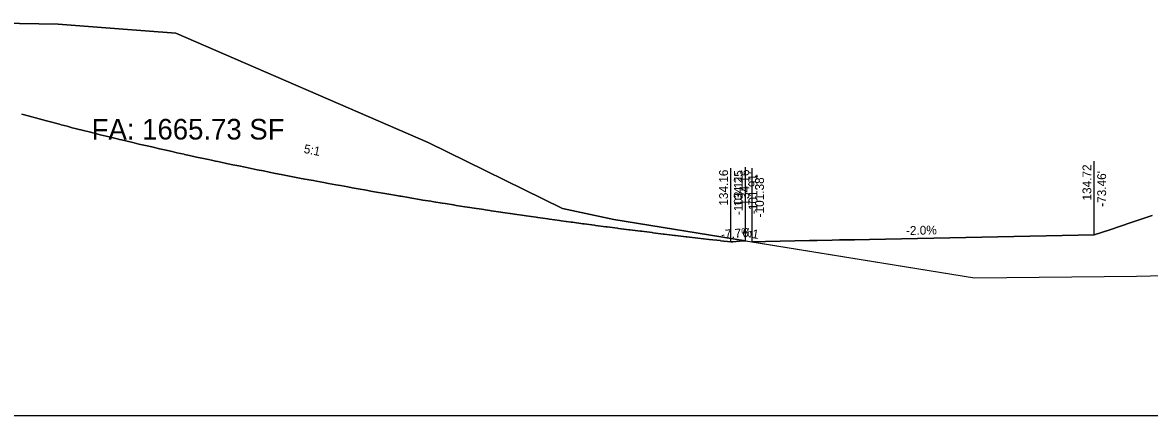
# Model space of a CAD drawing. Extents: x -26 to 4403, y -13 to 9578.
# Drawn here: x 2089.1 to 2181, y 0 to 32 of the extents above; entities that cross this region are included whole.
import ezdxf

# ---------------------------------------------------------------- set-up
doc = ezdxf.new("R2010")
doc.units = 0
for name, color, linetype in [('CONST_DCH', 7, 'Continuous'), ('DRAINAGE_SPUR_DIKES', 7, 'Continuous'), ('DTM_CORRIDOR', 7, 'Continuous'), ('DTM_X_GROUND', 7, 'Continuous'), ('XS_CELL', 7, 'Continuous'), ('XS_M_SHAPES_EARTHWORK', 7, 'Continuous'), ('XS_P_GROUND', 7, 'Continuous'), ('XS_P_TX_CLEARZONE', 7, 'Continuous'), ('XS_P_TX_FS_BS', 7, 'Continuous'), ('XS_SHEET_EW_TX_AREA', 7, 'Continuous')]:
    doc.layers.add(name, color=color, linetype=linetype)

msp = doc.modelspace()

# ---------------------------------------------------------------- linework, layer by layer
at = {"layer": 'DTM_X_GROUND'}
msp.add_lwpolyline([(2000, 18.081), (2016.738, 18.017), (2021.336, 18.271), (2026.377, 18.668), (2031.376, 19.287), (2044.087, 25.683), (2054.877, 30.415), (2060.086, 31.086), (2066.447, 31.939), (2073.829, 32.038), (2079.891, 32.016), (2085.664, 32.011), (2091.991, 31.895), (2096.952, 31.53), (2101.603, 31.182), (2122.191, 22.251), (2133.153, 16.884), (2137.339, 15.992), (2166.759, 11.226), (2179.976, 11.364), (2202.58, 11.905)], dxfattribs=at)
at = {"layer": 'XS_CELL'}
msp.add_line((2000, 0), (2250, 0), dxfattribs=at)
at = {"layer": 'XS_M_SHAPES_EARTHWORK'}
for points in [[(2085.664, 32.011), (2091.991, 31.895), (2096.952, 31.53), (2101.603, 31.182), (2122.191, 22.251), (2133.153, 16.884), (2137.339, 15.992), (2148.092, 14.25), (2147.869, 14.233), (2147.052, 14.17), (2146.955, 14.163), (2146.891, 14.158), (2146.04, 14.252), (2146.033, 14.253), (2145.123, 14.355), (2145.108, 14.357), (2144.204, 14.46), (2144.181, 14.463), (2143.284, 14.567), (2143.252, 14.571), (2142.361, 14.676), (2142.321, 14.681), (2141.437, 14.787), (2141.388, 14.793), (2140.511, 14.9), (2140.454, 14.908), (2139.584, 15.015), (2139.517, 15.024), (2138.654, 15.132), (2138.578, 15.142), (2137.723, 15.252), (2137.637, 15.263), (2136.789, 15.373), (2136.694, 15.385), (2135.854, 15.496), (2135.749, 15.51), (2134.916, 15.621), (2134.802, 15.636), (2133.977, 15.748), (2133.852, 15.765), (2133.035, 15.877), (2132.901, 15.896), (2132.091, 16.009), (2131.946, 16.029), (2131.145, 16.142), (2130.99, 16.164), (2130.197, 16.277), (2130.031, 16.302), (2129.247, 16.415), (2129.07, 16.441), (2128.294, 16.555), (2128.106, 16.583), (2127.339, 16.697), (2127.234, 16.712), (2126.833, 16.773), (2126.736, 16.787), (2126.345, 16.846), (2126.134, 16.878), (2125.412, 16.987), (2125.189, 17.022), (2124.487, 17.13), (2124.252, 17.167), (2123.57, 17.274), (2123.323, 17.314), (2122.66, 17.42), (2122.401, 17.462), (2121.757, 17.568), (2121.485, 17.613), (2120.859, 17.717), (2120.575, 17.766), (2119.966, 17.869), (2119.94, 17.874), (2119.887, 17.883), (2119.616, 17.93), (2118.973, 18.041), (2118.662, 18.096), (2117.977, 18.215), (2117.651, 18.273), (2116.987, 18.39), (2116.647, 18.451), (2116.003, 18.565), (2115.649, 18.629), (2115.025, 18.742), (2114.656, 18.809), (2114.051, 18.92), (2113.667, 18.991), (2113.082, 19.099), (2112.824, 19.148), (2112.454, 19.217), (2112.312, 19.244), (2112.12, 19.28), (2111.705, 19.36), (2111.161, 19.463), (2110.73, 19.547), (2110.196, 19.651), (2109.748, 19.739), (2109.223, 19.843), (2108.759, 19.936), (2108.244, 20.039), (2107.762, 20.137), (2107.257, 20.239), (2106.757, 20.342), (2106.263, 20.444), (2105.745, 20.552), (2105.262, 20.653), (2105.032, 20.702), (2104.827, 20.745), (2104.52, 20.81), (2104.276, 20.862), (2103.72, 20.982), (2103.296, 21.073), (2102.721, 21.199), (2102.304, 21.291), (2102.285, 21.295), (2102.272, 21.298), (2101.695, 21.427), (2101.3, 21.514), (2100.683, 21.654), (2100.284, 21.744), (2099.645, 21.891), (2099.256, 21.981), (2098.595, 22.134), (2098.217, 22.223), (2097.533, 22.384), (2097.166, 22.47), (2097.002, 22.509), (2096.918, 22.529), (2096.374, 22.66), (2096.163, 22.711), (2095.43, 22.89), (2095.171, 22.954), (2094.411, 23.145), (2094.17, 23.205), (2093.382, 23.408), (2093.159, 23.465), (2092.825, 23.553), (2092.738, 23.576), (2092.254, 23.704), (2092.114, 23.741), (2091.264, 23.969), (2091.044, 24.028), (2090.162, 24.27), (2089.964, 24.324), (2089.047, 24.581)], [(2181.257, 16.296), (2179.538, 15.723), (2178.674, 15.434), (2177.791, 15.14), (2176.537, 14.722), (2158.207, 14.356), (2156.984, 14.331), (2155.76, 14.307), (2155.148, 14.295), (2153.923, 14.27), (2153.31, 14.258), (2149.721, 14.186), (2148.803, 14.168), (2148.623, 14.164), (2166.759, 11.226), (2179.976, 11.364), (2202.58, 11.905)]]:
    msp.add_lwpolyline(points, dxfattribs=at)
at = {"layer": 'XS_P_GROUND'}
for points in [[(2133.153, 16.884), (2122.191, 22.251), (2101.603, 31.182), (2096.952, 31.53), (2091.991, 31.895), (2085.664, 32.011), (2079.891, 32.016), (2073.829, 32.038), (2066.447, 31.939), (2060.086, 31.086), (2054.877, 30.415), (2044.087, 25.683), (2031.376, 19.287), (2026.377, 18.668), (2021.336, 18.271), (2016.738, 18.017), (2013.602, 18.029)], [(2089.047, 24.581), (2089.964, 24.324), (2090.162, 24.27), (2091.044, 24.028), (2091.264, 23.969), (2092.114, 23.741), (2092.254, 23.704), (2092.738, 23.576), (2092.825, 23.553), (2093.159, 23.465), (2093.382, 23.408), (2094.17, 23.205), (2094.411, 23.145), (2095.171, 22.954), (2095.43, 22.89), (2096.163, 22.711), (2096.374, 22.66), (2096.918, 22.529), (2097.002, 22.509), (2097.166, 22.47), (2097.533, 22.384), (2098.217, 22.223), (2098.595, 22.134), (2099.256, 21.981), (2099.645, 21.891), (2100.284, 21.744), (2100.683, 21.654), (2101.3, 21.514), (2101.695, 21.427), (2102.272, 21.298), (2102.285, 21.295), (2102.304, 21.291), (2102.721, 21.199), (2103.296, 21.073), (2103.72, 20.982), (2104.276, 20.862), (2104.52, 20.81), (2104.827, 20.745), (2105.032, 20.702), (2105.262, 20.653), (2105.745, 20.552), (2106.263, 20.444), (2106.757, 20.342), (2107.257, 20.239), (2107.762, 20.137), (2108.244, 20.039), (2108.759, 19.936), (2109.223, 19.843), (2109.748, 19.739), (2110.196, 19.651), (2110.73, 19.547), (2111.161, 19.463), (2111.705, 19.36), (2112.12, 19.28), (2112.312, 19.244), (2112.454, 19.217), (2112.824, 19.148), (2113.082, 19.099), (2113.667, 18.991), (2114.051, 18.92), (2114.656, 18.809), (2115.025, 18.742), (2115.649, 18.629), (2116.003, 18.565), (2116.647, 18.451), (2116.987, 18.39), (2117.651, 18.273), (2117.977, 18.215), (2118.662, 18.096), (2118.973, 18.041), (2119.616, 17.93), (2119.887, 17.883), (2119.94, 17.874), (2119.966, 17.869), (2120.575, 17.766), (2120.859, 17.717), (2121.485, 17.613), (2121.757, 17.568), (2122.401, 17.462), (2122.66, 17.42), (2123.323, 17.314), (2123.57, 17.274), (2124.252, 17.167), (2124.487, 17.13), (2125.189, 17.022), (2125.412, 16.987), (2126.134, 16.878), (2126.345, 16.846), (2126.736, 16.787), (2126.833, 16.773), (2127.234, 16.712), (2127.339, 16.697), (2128.106, 16.583), (2128.294, 16.555), (2129.07, 16.441), (2129.247, 16.415), (2130.031, 16.302), (2130.197, 16.277), (2130.99, 16.164), (2131.145, 16.142), (2131.946, 16.029), (2132.091, 16.009), (2132.901, 15.896), (2133.035, 15.877), (2133.852, 15.765), (2133.977, 15.748), (2134.802, 15.636), (2134.916, 15.621), (2135.749, 15.51), (2135.854, 15.496), (2136.694, 15.385), (2136.789, 15.373), (2137.637, 15.263), (2137.723, 15.252), (2138.578, 15.142), (2138.654, 15.132), (2139.517, 15.024), (2139.584, 15.015), (2140.454, 14.908), (2140.511, 14.9), (2141.388, 14.793), (2141.437, 14.787), (2142.321, 14.681), (2142.361, 14.676), (2143.252, 14.571), (2143.284, 14.567), (2144.181, 14.463), (2144.204, 14.46), (2145.108, 14.357), (2145.123, 14.355), (2146.033, 14.253), (2146.04, 14.252), (2146.891, 14.158)], [(2089.047, 24.581), (2089.964, 24.324), (2090.162, 24.27), (2091.044, 24.028), (2091.264, 23.969), (2092.114, 23.741), (2092.254, 23.704), (2092.738, 23.576), (2092.825, 23.553), (2093.159, 23.465), (2093.382, 23.408), (2094.17, 23.205), (2094.411, 23.145), (2095.171, 22.954), (2095.43, 22.89), (2096.163, 22.711), (2096.374, 22.66), (2096.918, 22.529), (2097.002, 22.509), (2097.166, 22.47), (2097.533, 22.384), (2098.217, 22.223), (2098.595, 22.134), (2099.256, 21.981), (2099.645, 21.891), (2100.284, 21.744), (2100.683, 21.654), (2101.3, 21.514), (2101.695, 21.427), (2102.272, 21.298), (2102.285, 21.295), (2102.304, 21.291), (2102.721, 21.199), (2103.296, 21.073), (2103.72, 20.982), (2104.276, 20.862), (2104.52, 20.81), (2104.827, 20.745), (2105.032, 20.702), (2105.262, 20.653), (2105.745, 20.552), (2106.263, 20.444), (2106.757, 20.342), (2107.257, 20.239), (2107.762, 20.137), (2108.244, 20.039), (2108.759, 19.936), (2109.223, 19.843), (2109.748, 19.739), (2110.196, 19.651), (2110.73, 19.547), (2111.161, 19.463), (2111.705, 19.36), (2112.12, 19.28), (2112.312, 19.244), (2112.454, 19.217), (2112.824, 19.148), (2113.082, 19.099), (2113.667, 18.991), (2114.051, 18.92), (2114.656, 18.809), (2115.025, 18.742), (2115.649, 18.629), (2116.003, 18.565), (2116.647, 18.451), (2116.987, 18.39), (2117.651, 18.273), (2117.977, 18.215), (2118.662, 18.096), (2118.973, 18.041), (2119.616, 17.93), (2119.887, 17.883), (2119.94, 17.874), (2119.966, 17.869), (2120.575, 17.766), (2120.859, 17.717), (2121.485, 17.613), (2121.757, 17.568), (2122.401, 17.462), (2122.66, 17.42), (2123.323, 17.314), (2123.57, 17.274), (2124.252, 17.167), (2124.487, 17.13), (2125.189, 17.022), (2125.412, 16.987), (2126.134, 16.878), (2126.345, 16.846), (2126.736, 16.787), (2126.833, 16.773), (2127.234, 16.712), (2127.339, 16.697), (2128.106, 16.583), (2128.294, 16.555), (2129.07, 16.441), (2129.247, 16.415), (2130.031, 16.302), (2130.197, 16.277), (2130.99, 16.164), (2131.145, 16.142), (2131.946, 16.029), (2132.091, 16.009), (2132.901, 15.896), (2133.035, 15.877), (2133.852, 15.765), (2133.977, 15.748), (2134.802, 15.636), (2134.916, 15.621), (2135.749, 15.51), (2135.854, 15.496), (2136.694, 15.385), (2136.789, 15.373), (2137.637, 15.263), (2137.723, 15.252), (2138.578, 15.142), (2138.654, 15.132), (2139.517, 15.024), (2139.584, 15.015), (2140.454, 14.908), (2140.511, 14.9), (2141.388, 14.793), (2141.437, 14.787), (2142.321, 14.681), (2142.361, 14.676), (2143.252, 14.571), (2143.284, 14.567), (2144.181, 14.463), (2144.204, 14.46), (2145.108, 14.357), (2145.123, 14.355), (2146.033, 14.253), (2146.891, 14.158)], [(2148.092, 14.25), (2137.339, 15.992), (2133.153, 16.884)], [(2176.537, 14.722), (2177.791, 15.14), (2177.791, 15.14), (2177.791, 15.14), (2178.674, 15.434), (2178.674, 15.434), (2179.538, 15.723), (2179.538, 15.723), (2181.257, 16.296)], [(2148.623, 14.164), (2148.803, 14.168), (2149.721, 14.186), (2153.31, 14.258), (2153.923, 14.27), (2155.148, 14.295), (2155.76, 14.307), (2156.984, 14.331), (2158.207, 14.356), (2176.537, 14.722)], [(2146.891, 14.158), (2146.955, 14.163), (2147.052, 14.17), (2147.869, 14.233), (2148.092, 14.25)], [(2146.891, 14.158), (2146.955, 14.163), (2147.052, 14.17), (2147.869, 14.233), (2148.092, 14.25)]]:
    msp.add_lwpolyline(points, dxfattribs=at)
at = {"layer": 'XS_P_TX_CLEARZONE'}
for p, q in [((2148.092, 14.25), (2148.092, 20.25)), ((2148.092, 14.25), (2148.092, 20.25)), ((2148.092, 14.25), (2148.092, 20.25)), ((2148.092, 14.25), (2148.092, 20.25)), ((2148.092, 14.25), (2148.092, 20.25)), ((2148.092, 14.25), (2148.092, 20.25)), ((2176.537, 14.722), (2176.537, 20.722)), ((2176.537, 14.722), (2176.537, 20.722)), ((2176.537, 14.722), (2176.537, 20.722)), ((2146.891, 14.158), (2146.891, 20.158)), ((2146.891, 14.158), (2146.891, 20.158)), ((2146.891, 14.158), (2146.891, 20.158)), ((2148.623, 14.164), (2148.623, 20.164)), ((2148.623, 14.164), (2148.623, 20.164)), ((2148.623, 14.164), (2148.623, 20.164))]:
    msp.add_line(p, q, dxfattribs=at)

# ---------------------------------------------------------------- texts
at = {"layer": 'CONST_DCH'}
msp.add_text('X', height=0.12, dxfattribs=at).set_placement((2176.498, 14.662))
at = {"layer": 'DRAINAGE_SPUR_DIKES'}
msp.add_text('X', height=0.12, dxfattribs=at).set_placement((2148.053, 14.19))
at = {"layer": 'DTM_CORRIDOR'}
for p in [(2146.852, 14.098), (2148.584, 14.104)]:
    msp.add_text('X', height=0.12, dxfattribs=at).set_placement(p)
at = {"layer": 'XS_P_TX_CLEARZONE'}
for s, p in [('134.72', (2176.297, 17.527)), ('134.72', (2176.297, 17.527)), ('134.72', (2176.297, 17.527)), ('134.16', (2146.651, 17.103)), ('134.16', (2146.651, 17.103)), ('134.16', (2146.651, 17.103)), ("-103.11'", (2147.851, 16.327)), ("-103.11'", (2147.851, 16.327)), ("-103.11'", (2147.851, 16.327)), ('134.25', (2147.852, 17.054)), ('134.25', (2147.852, 17.054)), ('134.25', (2147.852, 17.054)), ('134.25', (2147.852, 17.054)), ('134.25', (2147.852, 17.054)), ('134.25', (2147.852, 17.054)), ('134.16', (2148.383, 17.11)), ('134.16', (2148.383, 17.11)), ('134.16', (2148.383, 17.11)), ("-101.91'", (2149.052, 16.419)), ("-101.91'", (2149.052, 16.419)), ("-101.91'", (2149.052, 16.419)), ("-101.91'", (2149.052, 16.419)), ("-101.91'", (2149.052, 16.419)), ("-101.91'", (2149.052, 16.419)), ("-101.38'", (2149.583, 16.152)), ("-101.38'", (2149.583, 16.152)), ("-101.38'", (2149.583, 16.152)), ("-73.46'", (2177.497, 17.016)), ("-73.46'", (2177.497, 17.016)), ("-73.46'", (2177.497, 17.016))]:
    msp.add_text(s, height=0.72, rotation=90, dxfattribs=at).set_placement(p)
at = {"layer": 'XS_P_TX_FS_BS'}
for s, rotation, p in [('5:1', 348.72822, (2111.999, 21.418)), ('5:1', 348.72822, (2111.999, 21.418)), ('5:1', 348.72822, (2111.999, 21.418)), ('-7.7%', 4.39664, (2146.105, 14.398)), ('-7.7%', 4.39664, (2146.105, 14.398)), ('-7.7%', 4.39664, (2146.105, 14.398)), ('6:1', 350.79792, (2147.784, 14.604)), ('6:1', 350.79792, (2147.784, 14.604)), ('6:1', 350.79792, (2147.784, 14.604)), ('-2.0%', 1.14576, (2161.178, 14.715)), ('-2.0%', 1.14576, (2161.178, 14.715)), ('-2.0%', 1.14576, (2161.178, 14.715))]:
    msp.add_text(s, height=0.72, rotation=rotation, dxfattribs=at).set_placement(p)
at = {"layer": 'XS_SHEET_EW_TX_AREA'}
msp.add_text('FA: 1665.73 SF', height=1.68, dxfattribs=at).set_placement((2094.736, 22.5))

doc.saveas('drawing.dxf')
